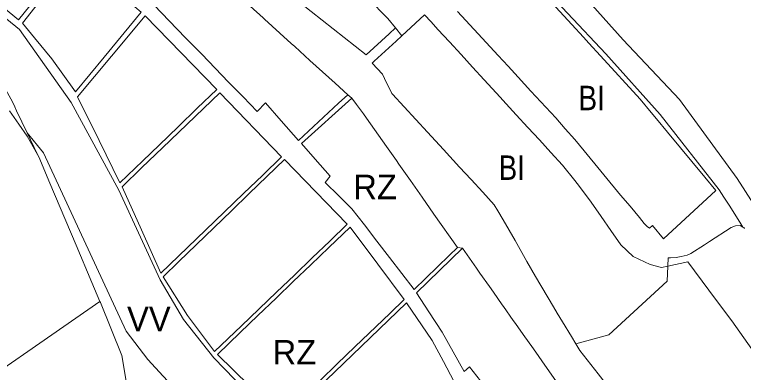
# Model space of a CAD drawing. Extents: x -650451 to -642268, y -1075216 to -1066610.
# Drawn here: x -646422 to -646064, y -1072296.3 to -1072120.7 of the extents above; entities that cross this region are included whole.
import ezdxf

# ---------------------------------------------------------------- set-up
doc = ezdxf.new("R2010")
doc.units = 0
doc.header["$LTSCALE"] = 4.8
for name, color, linetype, lineweight in [('15', 7, 'Continuous', 13), ('2', 7, 'Continuous', 13), ('24', 7, 'Continuous', 13), ('40', 7, 'Continuous', 13), ('43', 7, 'Continuous', 13), ('45', 7, 'Continuous', 13), ('46', 7, 'Continuous', 13), ('48', 7, 'Continuous', 13), ('6', 7, 'Continuous', 13)]:
    doc.layers.add(name, color=color, linetype=linetype, lineweight=lineweight)
doc.layers.add('62', color=7, linetype='Continuous')

msp = doc.modelspace()

# ---------------------------------------------------------------- linework, layer by layer
at = {"layer": '15'}
for points in [[(-646000.45, -1072615.28), (-645999.14, -1072611.29), (-646006.21, -1072593.04), (-646009.27, -1072582.89), (-646016.46, -1072568.07), (-646027.37, -1072549.05), (-646034.83, -1072536.97), (-646054.33, -1072506.16), (-646088.86, -1072457.93), (-646132.34, -1072412.37), (-646164.02, -1072390), (-646206.07, -1072366.43), (-646248.46, -1072343.52), (-646270.62, -1072332.33), (-646289.9, -1072320.26), (-646308.74, -1072304.97), (-646324.17, -1072289.15), (-646339.07, -1072270.33), (-646350.46, -1072250.81), (-646370.83, -1072206.8), (-646394.24, -1072163.81), (-646419.55, -1072128.03), (-646512.21, -1072052.57)], [(-646406.46, -1072068.39), (-646402.15, -1072077.6), (-646393.18, -1072088.66), (-646359.91, -1072113.46), (-646362.33, -1072107.88), (-646361.48, -1072108.67), (-646353.47, -1072116.17), (-646345.99, -1072123.86), (-646338.01, -1072132.07), (-646330.1, -1072140.22), (-646316.86, -1072153.83), (-646309.8, -1072161.1), (-646302.8, -1072168.3), (-646298.75, -1072164.1), (-646290.99, -1072172.91), (-646282.52, -1072182.54), (-646262.9, -1072164.17), (-646258.35, -1072160.04), (-646256.42, -1072161.7)], [(-646181.609, -1072086.079), (-646169.22, -1072099.97), (-646131.65, -1072140.05)], [(-646234.9, -1072127.22), (-646238.72, -1072122.6), (-646248.39, -1072112.76), (-646239.86, -1072099.92), (-646249.71, -1072089.21)], [(-646204.46, -1072119.17), (-646194.35, -1072130.11), (-646184.48, -1072140.8), (-646179.6, -1072146.08), (-646174.71, -1072151.38), (-646168.36, -1072158.25), (-646161.13, -1072166.08), (-646156.19, -1072171.44), (-646151.51, -1072176.71), (-646146.89, -1072182.04), (-646142.27, -1072187.57), (-646124.33, -1072209.25), (-646119.73, -1072214.8), (-646115.14, -1072220.36), (-646112.76, -1072223.22), (-646111.38, -1072224.63), (-646110.19, -1072225.59), (-646108.74, -1072224.25), (-646103.34, -1072230.77), (-646077.57, -1072207.09), (-646082.96, -1072200.57), (-646101.36, -1072178.37), (-646106.75, -1072171.85), (-646109.31, -1072168.77), (-646114.7, -1072162.25), (-646134.19, -1072141.04), (-646139.91, -1072134.82), (-646141.26, -1072133.34), (-646142.61, -1072131.87), (-646148.33, -1072125.65), (-646158.07, -1072115.05)], [(-646101.18, -1072244.23), (-646104.22, -1072244.89), (-646109.89, -1072243.31), (-646118.15, -1072239.49), (-646124.2, -1072233.64), (-646129.07, -1072226.71), (-646133.87, -1072219.72), (-646138.75, -1072212.79), (-646144.61, -1072205.07), (-646146.83, -1072202.19), (-646152.86, -1072194.62), (-646158.54, -1072188.44), (-646164.22, -1072182.25), (-646169.91, -1072176.07), (-646175.59, -1072169.88), (-646182.12, -1072162.78), (-646183.47, -1072161.3), (-646191.35, -1072152.72), (-646197.04, -1072146.54), (-646202.72, -1072140.35), (-646208.4, -1072134.17), (-646214.08, -1072127.98), (-646217.46, -1072124.31), (-646220.61, -1072120.88), (-646231.72, -1072131.08), (-646234.9, -1072127.22)], [(-646131.65, -1072140.05), (-646104.85, -1072169.81), (-646075.91, -1072206.65), (-646073.62, -1072210.24), (-646071.06, -1072214.28), (-646065.77, -1072222.6), (-646064.24, -1072225.01)], [(-646256.42, -1072161.7), (-646281.09, -1072184.04), (-646274.38, -1072191.62), (-646267.04, -1072199.93), (-646269.39, -1072203.17), (-646262.75, -1072209.7), (-646256.28, -1072216.06), (-646250.19, -1072223.93), (-646244.07, -1072231.82), (-646237.85, -1072239.85), (-646231.75, -1072247.73), (-646225.67, -1072255.58), (-646208.61, -1072238.99), (-646204.52, -1072235.01), (-646202.08, -1072235.38)], [(-646384.056, -1072252.138), (-646391.77, -1072233.91), (-646399.6, -1072215.39), (-646404.67, -1072203.42), (-646410.14, -1072190.49), (-646410.68, -1072189.36), (-646415.75, -1072178.82)], [(-646415.75, -1072178.82), (-646407.81, -1072188.6), (-646367.24, -1072276.07), (-646356.62, -1072289.89), (-646349.05, -1072298.16), (-646326.33, -1072322.56), (-646298.76, -1072344.13), (-646267.31, -1072361.39), (-646225.13, -1072384.18), (-646183.23, -1072407.45), (-646151.34, -1072429.6), (-646108.36, -1072475.46), (-646073.49, -1072523.45), (-646054.2, -1072554.48), (-646040.96, -1072577.06), (-646028.02, -1072609.24), (-646016.23, -1072641.16), (-646003.73, -1072680.75), (-645989.39, -1072712.38), (-645973.9, -1072738.22), (-645970.61, -1072747.97), (-645967.91, -1072767.31), (-645967.22, -1072787.26), (-645943.65, -1072789.47)], [(-646064.24, -1072225.01), (-646065.64, -1072224.26), (-646067.87, -1072224.34), (-646070.02, -1072225.18), (-646080.67, -1072232.05), (-646083.18, -1072233.66), (-646089.83, -1072237.95), (-646091.73, -1072238.71), (-646094.63, -1072239.5), (-646097.13, -1072239.87), (-646099.81, -1072240.09), (-646100.98, -1072240.01), (-646101.18, -1072244.23)], [(-646202.08, -1072235.38), (-646224.64, -1072257.23), (-646218.5, -1072266.6), (-646211.97, -1072276.57), (-646206.54, -1072286.21), (-646201.14, -1072295.81), (-646198.51, -1072293.55), (-646191.42, -1072302.72), (-646184.36, -1072311.83), (-646177.12, -1072321.19), (-646179.53, -1072323.27), (-646172.77, -1072331.06), (-646165.77, -1072339.12), (-646162.06, -1072343.4), (-646159.76, -1072344.16), (-646158.29, -1072345.96), (-646155.77, -1072349.02), (-646156.78, -1072349.77), (-646152.42, -1072355.16), (-646145.57, -1072363.62), (-646124.57, -1072345.05), (-646116.89, -1072345.3)], [(-646366.62, -1072303.53), (-646369.35, -1072287.95), (-646379.86, -1072262.05), (-646380.12, -1072261.44), (-646384.056, -1072252.138)]]:
    msp.add_lwpolyline(points, dxfattribs=at)
for points in [[(-646396.16, -1072093.12), (-646404.5, -1072081.26), (-646409.87, -1072073.68), (-646423.17, -1072054.9), (-646431.45, -1072065.31), (-646439.1, -1072074.94), (-646446.74, -1072084.55), (-646454.82, -1072094.71), (-646437.75, -1072108.75), (-646420.06, -1072123.31), (-646411.77, -1072112.84), (-646404.2, -1072103.27)], [(-646359.74, -1072119.55), (-646375.35, -1072106.35), (-646394.62, -1072095.11), (-646402.31, -1072104.86), (-646418.13, -1072124.9), (-646412.18, -1072132.12), (-646403.75, -1072142.38), (-646392.06, -1072158.59), (-646377.99, -1072141.59)], [(-646357.8, -1072121.32), (-646374.38, -1072141.15), (-646391.02, -1072161.06), (-646380.5, -1072182.54), (-646370.34, -1072203.29), (-646359.02, -1072192.42), (-646351.05, -1072184.77), (-646341.68, -1072175.77), (-646332.25, -1072166.72), (-646322.64, -1072157.49)], [(-646321.23, -1072159.05), (-646349.33, -1072186.1), (-646359.42, -1072195.82), (-646369.17, -1072205.2), (-646359.65, -1072226.35), (-646354.89, -1072236.93), (-646350.13, -1072247.52), (-646328.19, -1072226.43), (-646309.52, -1072208.48), (-646300.14, -1072199.47), (-646290.82, -1072190.5)], [(-646289.45, -1072191.87), (-646298.12, -1072200.24), (-646306.75, -1072208.58), (-646315.47, -1072217.01), (-646324.05, -1072225.29), (-646341.28, -1072241.94), (-646349.03, -1072249.42), (-646337.06, -1072268.4), (-646323.76, -1072286.05), (-646310.6, -1072273.44), (-646293.28, -1072256.84), (-646284.57, -1072248.5), (-646275.87, -1072240.15), (-646267.19, -1072231.84), (-646258.57, -1072223.58), (-646274.04, -1072207.69)], [(-646257.17, -1072225.02), (-646267.59, -1072235), (-646276.46, -1072243.48), (-646285.1, -1072251.76), (-646293.54, -1072259.83), (-646302.49, -1072268.4), (-646311.21, -1072276.74), (-646322.37, -1072287.43), (-646306.56, -1072302.91), (-646289.72, -1072317.17), (-646280.78, -1072308.62), (-646271.98, -1072300.2), (-646263.55, -1072292.13), (-646254.8, -1072283.76), (-646237.45, -1072267.15), (-646230.6, -1072260.59), (-646243.64, -1072243.12)], [(-646229.47, -1072262.11), (-646247.38, -1072279.35), (-646256.03, -1072287.68), (-646264.64, -1072295.96), (-646287.88, -1072318.32), (-646278.46, -1072324.39), (-646268.81, -1072330.59), (-646248.36, -1072341.06), (-646234.63, -1072327.85), (-646225.91, -1072319.47), (-646206.31, -1072300.61), (-646211.41, -1072290.93), (-646216.82, -1072280.7)]]:
    msp.add_lwpolyline(points, close=True, dxfattribs=at)
at = {"layer": '2'}
for points in [[(-646158.07, -1072115.05), (-646148.33, -1072125.65), (-646142.61, -1072131.87), (-646141.26, -1072133.34), (-646139.91, -1072134.82), (-646134.19, -1072141.04), (-646114.7, -1072162.25), (-646109.31, -1072168.77), (-646106.75, -1072171.85), (-646101.36, -1072178.37), (-646082.96, -1072200.57), (-646077.57, -1072207.09), (-646103.34, -1072230.77), (-646108.74, -1072224.25), (-646110.19, -1072225.59), (-646111.38, -1072224.63), (-646112.76, -1072223.22), (-646115.14, -1072220.36), (-646119.73, -1072214.8), (-646124.33, -1072209.25), (-646142.27, -1072187.57), (-646146.89, -1072182.04), (-646151.51, -1072176.71), (-646156.19, -1072171.44), (-646161.13, -1072166.08), (-646168.36, -1072158.25), (-646174.71, -1072151.38), (-646179.6, -1072146.08), (-646184.48, -1072140.8), (-646194.35, -1072130.11), (-646204.46, -1072119.17)], [(-646231.72, -1072131.08), (-646220.61, -1072120.88), (-646217.46, -1072124.31), (-646214.08, -1072127.98), (-646208.4, -1072134.17), (-646202.72, -1072140.35), (-646197.04, -1072146.54), (-646191.35, -1072152.72), (-646183.47, -1072161.3), (-646182.12, -1072162.78), (-646175.59, -1072169.88), (-646169.91, -1072176.07), (-646164.22, -1072182.25), (-646158.54, -1072188.44), (-646152.86, -1072194.62), (-646146.83, -1072202.19), (-646144.61, -1072205.07), (-646138.75, -1072212.79), (-646133.87, -1072219.72), (-646129.07, -1072226.71), (-646124.2, -1072233.64), (-646118.15, -1072239.49), (-646109.89, -1072243.31), (-646104.22, -1072244.89), (-646101.18, -1072244.23)], [(-646246.39, -1072144.56), (-646245.39, -1072143.64), (-646234.64, -1072133.77), (-646231.72, -1072131.08)], [(-646211.37, -1072186.94), (-646219.27, -1072178.37), (-646236.35, -1072159.85), (-646236.66, -1072159.51), (-646240.33, -1072152.1), (-646241.37, -1072150.02), (-646246.39, -1072144.56)], [(-646192.09, -1072207.86), (-646197.78, -1072201.68), (-646203.48, -1072195.51), (-646211.37, -1072186.94)], [(-646176.21, -1072231.64), (-646182.05, -1072221.45), (-646184.57, -1072217.04), (-646186.39, -1072214.03), (-646192.09, -1072207.86)], [(-646101.18, -1072244.23), (-646100.98, -1072240.01), (-646099.81, -1072240.09), (-646097.13, -1072239.87), (-646094.63, -1072239.5), (-646091.73, -1072238.71), (-646089.83, -1072237.95), (-646083.18, -1072233.66), (-646080.67, -1072232.05), (-646070.02, -1072225.18), (-646067.87, -1072224.34), (-646065.64, -1072224.26), (-646064.24, -1072225.01)], [(-646064.24, -1072225.01), (-646063.86, -1072225.22), (-646063.53, -1072225.6)], [(-646157.3, -1072264.05), (-646166.08, -1072249.31), (-646170.37, -1072241.84), (-646176.21, -1072231.64)], [(-646101.18, -1072244.23), (-646101.53, -1072251.45), (-646130.2, -1072277.79), (-646146.27, -1072282.34), (-646148.45, -1072278.73)], [(-646014.64, -1072358.74), (-646016.43, -1072355.88), (-646026.55, -1072339.67), (-646037.37, -1072322.92), (-646048.32, -1072305.81), (-646057.93, -1072287.58), (-646069.73, -1072270.99), (-646071.3, -1072268.92), (-646081.08, -1072256.01), (-646091.27, -1072242.07), (-646101.18, -1072244.23)], [(-646504.244, -1072357.026), (-646485.656, -1072338.908), (-646473.069, -1072327.765), (-646465.227, -1072321.127), (-646459.03, -1072316.137), (-646380.12, -1072261.44)], [(-646380.12, -1072261.44), (-646379.86, -1072262.05), (-646369.35, -1072287.95), (-646366.62, -1072303.53)], [(-646148.45, -1072278.73), (-646152.81, -1072271.52), (-646155.44, -1072267.16), (-646157.3, -1072264.05)]]:
    msp.add_lwpolyline(points, dxfattribs=at)
at = {"layer": '24'}
for points in [[(-646194.191, -1072055.797), (-646159.66, -1072092.31), (-646123.06, -1072133.18), (-646095.44, -1072162.47)], [(-646131.65, -1072140.05), (-646169.22, -1072099.97), (-646181.609, -1072086.079)], [(-646064.24, -1072225.01), (-646065.77, -1072222.6), (-646071.06, -1072214.28), (-646073.62, -1072210.24), (-646075.91, -1072206.65), (-646104.85, -1072169.81), (-646131.65, -1072140.05)], [(-646095.44, -1072162.47), (-646067.08, -1072201.18), (-646008.065, -1072293.22), (-645982.874, -1072332.508), (-645979.68, -1072337.49), (-645971.13, -1072349.41), (-645919.08, -1072421.96), (-645916.34, -1072426.55), (-645898.28, -1072448.47)], [(-646063.53, -1072225.6), (-646063.86, -1072225.22), (-646064.24, -1072225.01)]]:
    msp.add_lwpolyline(points, dxfattribs=at)
at = {"layer": '40'}
for points in [[(-646249.71, -1072089.21), (-646239.86, -1072099.92), (-646248.39, -1072112.76), (-646238.72, -1072122.6), (-646234.9, -1072127.22)], [(-646234.9, -1072127.22), (-646238.03, -1072130.1), (-646249.36, -1072140.5), (-646287.16, -1072110.52)], [(-646433.16, -1072145.61), (-646422.94, -1072163.48), (-646421.9, -1072166.01), (-646420.97, -1072167.95), (-646415.75, -1072178.82), (-646410.68, -1072189.36)], [(-646410.68, -1072189.36), (-646415.84, -1072180.43), (-646419.83, -1072174.51), (-646424.56, -1072167.96)]]:
    msp.add_lwpolyline(points, dxfattribs=at)
at = {"layer": '43'}
for points in [[(-646320.51, -1072084.13), (-646312.51, -1072090.43), (-646307.16, -1072094.67), (-646293.83, -1072105.24), (-646287.16, -1072110.52), (-646249.36, -1072140.5)], [(-646267.64, -1072151.6), (-646276.92, -1072143.18), (-646284.31, -1072136.47), (-646286.09, -1072134.85), (-646291.65, -1072129.81), (-646299.17, -1072122.98), (-646299.95, -1072122.27), (-646306.22, -1072116.58)], [(-646249.36, -1072140.5), (-646238.03, -1072130.1), (-646234.9, -1072127.22), (-646231.72, -1072131.08), (-646234.64, -1072133.77), (-646245.39, -1072143.64), (-646246.39, -1072144.56), (-646241.37, -1072150.02), (-646240.33, -1072152.1)], [(-646258.35, -1072160.04), (-646264.53, -1072154.43), (-646267.64, -1072151.6)], [(-646240.33, -1072152.1), (-646236.66, -1072159.51), (-646236.35, -1072159.85), (-646219.27, -1072178.37), (-646211.37, -1072186.94)], [(-646250.54, -1072169.43), (-646253.99, -1072164.89), (-646256.42, -1072161.7), (-646258.35, -1072160.04)], [(-646233.19, -1072194.16), (-646234.49, -1072192.31), (-646239.32, -1072185.42), (-646249.07, -1072171.52), (-646250.54, -1072169.43)], [(-646211.37, -1072186.94), (-646203.48, -1072195.51), (-646197.78, -1072201.68), (-646192.09, -1072207.86), (-646186.39, -1072214.03)], [(-646204.52, -1072235.01), (-646216.04, -1072218.6), (-646221.81, -1072210.37), (-646227.62, -1072202.1), (-646233.19, -1072194.16)], [(-646186.39, -1072214.03), (-646184.57, -1072217.04), (-646182.05, -1072221.45), (-646176.21, -1072231.64), (-646170.37, -1072241.84)], [(-646186.83, -1072256.95), (-646188.78, -1072254.2), (-646193.5, -1072247.52), (-646195.15, -1072245.18), (-646202.08, -1072235.38), (-646204.52, -1072235.01)], [(-646170.37, -1072241.84), (-646166.08, -1072249.31), (-646157.3, -1072264.05), (-646155.44, -1072267.16)], [(-646172.17, -1072277.7), (-646175.95, -1072272.36), (-646177.05, -1072270.8), (-646181.94, -1072263.89), (-646182.5, -1072263.09), (-646186.83, -1072256.95)], [(-646155.44, -1072267.16), (-646152.81, -1072271.52), (-646148.45, -1072278.73), (-646146.27, -1072282.34)], [(-646149.48, -1072309.81), (-646156.16, -1072300.36), (-646160.44, -1072294.29), (-646167.16, -1072284.79), (-646172.17, -1072277.7)], [(-646146.27, -1072282.34), (-646144.38, -1072285.47), (-646135.43, -1072296.99), (-646129.15, -1072305.06)]]:
    msp.add_lwpolyline(points, dxfattribs=at)
at = {"layer": '45'}
for points in [[(-646512.21, -1072052.57), (-646419.55, -1072128.03), (-646394.24, -1072163.81), (-646370.83, -1072206.8), (-646350.46, -1072250.81), (-646339.07, -1072270.33), (-646324.17, -1072289.15), (-646308.74, -1072304.97), (-646289.9, -1072320.26), (-646270.62, -1072332.33), (-646248.46, -1072343.52), (-646206.07, -1072366.43), (-646164.02, -1072390), (-646132.34, -1072412.37), (-646088.86, -1072457.93), (-646054.33, -1072506.16), (-646034.83, -1072536.97), (-646027.37, -1072549.05), (-646016.46, -1072568.07), (-646009.27, -1072582.89), (-646006.21, -1072593.04), (-645999.14, -1072611.29), (-646000.45, -1072615.28)], [(-646415.75, -1072178.82), (-646420.97, -1072167.95), (-646421.9, -1072166.01), (-646422.94, -1072163.48), (-646433.16, -1072145.61)], [(-645943.65, -1072789.47), (-645967.22, -1072787.26), (-645967.91, -1072767.31), (-645970.61, -1072747.97), (-645973.9, -1072738.22), (-645989.39, -1072712.38), (-646003.73, -1072680.75), (-646016.23, -1072641.16), (-646028.02, -1072609.24), (-646040.96, -1072577.06), (-646054.2, -1072554.48), (-646073.49, -1072523.45), (-646108.36, -1072475.46), (-646151.34, -1072429.6), (-646183.23, -1072407.45), (-646225.13, -1072384.18), (-646267.31, -1072361.39), (-646298.76, -1072344.13), (-646326.33, -1072322.56), (-646349.05, -1072298.16), (-646356.62, -1072289.89), (-646367.24, -1072276.07), (-646407.81, -1072188.6), (-646415.75, -1072178.82)]]:
    msp.add_lwpolyline(points, dxfattribs=at)
at = {"layer": '46'}
for points in [[(-646123.06, -1072133.18), (-646159.66, -1072092.31), (-646194.191, -1072055.797)], [(-646008.065, -1072293.22), (-646067.08, -1072201.18), (-646095.44, -1072162.47), (-646123.06, -1072133.18)]]:
    msp.add_lwpolyline(points, dxfattribs=at)
at = {"layer": '48'}
for points in [[(-646146.27, -1072282.34), (-646130.2, -1072277.79), (-646101.53, -1072251.45), (-646101.18, -1072244.23)], [(-646101.18, -1072244.23), (-646091.27, -1072242.07), (-646081.08, -1072256.01), (-646071.3, -1072268.92), (-646069.73, -1072270.99), (-646057.93, -1072287.58), (-646048.32, -1072305.81), (-646037.37, -1072322.92), (-646026.55, -1072339.67), (-646016.43, -1072355.88), (-646014.64, -1072358.74), (-646042.65, -1072381.23)], [(-646129.15, -1072305.06), (-646135.43, -1072296.99), (-646144.38, -1072285.47), (-646146.27, -1072282.34)]]:
    msp.add_lwpolyline(points, dxfattribs=at)
at = {"layer": '6'}
msp.add_line((-646202.08, -1072235.38), (-646195.15, -1072245.18), dxfattribs=at)
for points in [[(-646396.16, -1072093.12), (-646404.2, -1072103.27), (-646411.77, -1072112.84), (-646420.06, -1072123.31), (-646437.75, -1072108.75), (-646454.82, -1072094.71), (-646446.74, -1072084.55), (-646439.1, -1072074.94), (-646431.45, -1072065.31), (-646423.17, -1072054.9), (-646409.87, -1072073.68), (-646404.5, -1072081.26)], [(-646359.74, -1072119.55), (-646377.99, -1072141.59), (-646392.06, -1072158.59), (-646403.75, -1072142.38), (-646412.18, -1072132.12), (-646418.13, -1072124.9), (-646402.31, -1072104.86), (-646394.62, -1072095.11), (-646375.35, -1072106.35)], [(-646357.8, -1072121.32), (-646322.64, -1072157.49), (-646332.25, -1072166.72), (-646341.68, -1072175.77), (-646351.05, -1072184.77), (-646359.02, -1072192.42), (-646370.34, -1072203.29), (-646380.5, -1072182.54), (-646391.02, -1072161.06), (-646374.38, -1072141.15)], [(-646321.23, -1072159.05), (-646290.82, -1072190.5), (-646300.14, -1072199.47), (-646309.52, -1072208.48), (-646328.19, -1072226.43), (-646350.13, -1072247.52), (-646354.89, -1072236.93), (-646359.65, -1072226.35), (-646369.17, -1072205.2), (-646359.42, -1072195.82), (-646349.33, -1072186.1)], [(-646289.45, -1072191.87), (-646274.04, -1072207.69), (-646258.57, -1072223.58), (-646267.19, -1072231.84), (-646275.87, -1072240.15), (-646284.57, -1072248.5), (-646293.28, -1072256.84), (-646310.6, -1072273.44), (-646323.76, -1072286.05), (-646337.06, -1072268.4), (-646349.03, -1072249.42), (-646341.28, -1072241.94), (-646324.05, -1072225.29), (-646315.47, -1072217.01), (-646306.75, -1072208.58), (-646298.12, -1072200.24)], [(-646257.17, -1072225.02), (-646243.64, -1072243.12), (-646230.6, -1072260.59), (-646237.45, -1072267.15), (-646254.8, -1072283.76), (-646263.55, -1072292.13), (-646271.98, -1072300.2), (-646280.78, -1072308.62), (-646289.72, -1072317.17), (-646306.56, -1072302.91), (-646322.37, -1072287.43), (-646311.21, -1072276.74), (-646302.49, -1072268.4), (-646293.54, -1072259.83), (-646285.1, -1072251.76), (-646276.46, -1072243.48), (-646267.59, -1072235)], [(-646229.47, -1072262.11), (-646216.82, -1072280.7), (-646211.41, -1072290.93), (-646206.31, -1072300.61), (-646225.91, -1072319.47), (-646234.63, -1072327.85), (-646248.36, -1072341.06), (-646268.81, -1072330.59), (-646278.46, -1072324.39), (-646287.88, -1072318.32), (-646264.64, -1072295.96), (-646256.03, -1072287.68), (-646247.38, -1072279.35)]]:
    msp.add_lwpolyline(points, close=True, dxfattribs=at)
for points in [[(-646258.35, -1072160.04), (-646262.9, -1072164.17), (-646282.52, -1072182.54), (-646290.99, -1072172.91), (-646298.75, -1072164.1), (-646302.8, -1072168.3), (-646309.8, -1072161.1), (-646316.86, -1072153.83), (-646330.1, -1072140.22), (-646338.01, -1072132.07), (-646345.99, -1072123.86), (-646353.47, -1072116.17), (-646361.48, -1072108.67), (-646362.33, -1072107.88), (-646359.91, -1072113.46), (-646393.18, -1072088.66), (-646402.15, -1072077.6), (-646406.46, -1072068.39)], [(-646321.85, -1072102.39), (-646313.68, -1072109.81), (-646312.43, -1072110.94), (-646306.22, -1072116.58), (-646299.95, -1072122.27), (-646299.17, -1072122.98), (-646291.65, -1072129.81)], [(-646291.65, -1072129.81), (-646286.09, -1072134.85), (-646284.31, -1072136.47), (-646276.92, -1072143.18), (-646267.64, -1072151.6)], [(-646267.64, -1072151.6), (-646264.53, -1072154.43), (-646258.35, -1072160.04)], [(-646204.52, -1072235.01), (-646208.61, -1072238.99), (-646225.67, -1072255.58), (-646231.75, -1072247.73), (-646237.85, -1072239.85), (-646244.07, -1072231.82), (-646250.19, -1072223.93), (-646256.28, -1072216.06), (-646262.75, -1072209.7), (-646269.39, -1072203.17), (-646267.04, -1072199.93), (-646274.38, -1072191.62), (-646281.09, -1072184.04), (-646256.42, -1072161.7)], [(-646256.42, -1072161.7), (-646253.99, -1072164.89), (-646250.54, -1072169.43)], [(-646250.54, -1072169.43), (-646249.07, -1072171.52), (-646239.32, -1072185.42), (-646234.49, -1072192.31), (-646233.19, -1072194.16), (-646227.62, -1072202.1), (-646221.81, -1072210.37)], [(-646221.81, -1072210.37), (-646216.04, -1072218.6), (-646204.52, -1072235.01)], [(-646124.57, -1072345.05), (-646145.57, -1072363.62), (-646152.42, -1072355.16), (-646156.78, -1072349.77), (-646155.77, -1072349.02), (-646158.29, -1072345.96), (-646159.76, -1072344.16), (-646162.06, -1072343.4), (-646165.77, -1072339.12), (-646172.77, -1072331.06), (-646179.53, -1072323.27), (-646177.12, -1072321.19), (-646184.36, -1072311.83), (-646191.42, -1072302.72), (-646198.51, -1072293.55), (-646201.14, -1072295.81), (-646206.54, -1072286.21), (-646211.97, -1072276.57), (-646218.5, -1072266.6), (-646224.64, -1072257.23), (-646202.08, -1072235.38)], [(-646195.15, -1072245.18), (-646193.5, -1072247.52), (-646188.78, -1072254.2), (-646186.83, -1072256.95)], [(-646186.83, -1072256.95), (-646182.5, -1072263.09), (-646181.94, -1072263.89), (-646177.05, -1072270.8), (-646175.95, -1072272.36), (-646172.17, -1072277.7), (-646167.16, -1072284.79)], [(-646167.16, -1072284.79), (-646160.44, -1072294.29), (-646156.16, -1072300.36), (-646149.48, -1072309.81)]]:
    msp.add_lwpolyline(points, dxfattribs=at)

# ---------------------------------------------------------------- texts
at = {"layer": '62', "width": 0.85}
for p in [(-646145.006, -1072167.651), (-646184.251, -1072201.832)]:
    msp.add_text('BI', height=12, dxfattribs=at).set_placement(p)
at = {"layer": '62'}
for s, p in [('RZ', (-646255.626, -1072211.293)), ('VV', (-646366.738, -1072276.072)), ('RZ', (-646295.247, -1072292.394))]:
    msp.add_text(s, height=12, dxfattribs=at).set_placement(p)

doc.saveas('drawing.dxf')
